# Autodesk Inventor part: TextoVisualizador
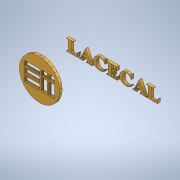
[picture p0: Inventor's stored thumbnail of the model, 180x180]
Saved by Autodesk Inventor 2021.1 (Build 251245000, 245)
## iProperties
Created: 2021-06
Part Number: TextoVisualizador
Material: Genérico
Document SubType Name: Modeling
Designer: Ricardo
Density: 1 g/cm^3
Appearance: Valor por defecto
Author: Ricardo
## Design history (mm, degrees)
sketch "Boceto1"
  geometry: L1 (-51.459, -7.217)-(-53.759, -7.217); L2 (-47.959, -7.217)-(-50.259, -7.217); L3 (-45.659, 2.183)-(-45.659, -2.517); L4 (-45.659, -7.217)-(-47.959, -7.217); L5 (-47.959, 2.183)-(-45.659, 2.183); L6 (-47.959, 7.383)-(-45.659, 7.383); L7 (-50.259, -2.517)-(-50.259, 2.183); L8 (-51.459, 7.383)-(-51.459, 5.358); L9 (-53.759, 7.383)-(-51.459, 7.383); L10 (-56.059, -2.517)-(-56.059, 2.183); L11 (-56.059, 7.383)-(-53.759, 7.383); L12 (-53.759, 3.333)-(-56.059, 3.333); L13 (-50.259, 5.358)-(-50.259, 7.383); L14 (-56.059, 5.358)-(-56.059, 7.383); L15 (32, -25.5)-(32, 25.5); L16 (-73.2, -43.7)-(73.2, -43.7); L17 (73.2, 43.7)-(-73.2, 43.7); L18 (73.2, 43.7)-(-73.2, 43.7); L19 (77.187, 25.393)-(-77.213, 25.607); L20 (-77.187, 43.807)-(77.213, 43.593); L21 (32, 25.5)-(-37, 25.5); L22 (32, 25.5)-(-37, 25.5); L23 (32, 25.5)-(-37, 25.5); L24 (-37, -25.5)-(32, -25.5); L25 (-37, -25.5)-(32, -25.5); L26 (-37, 25.5)-(-37, -25.5); L27 (-45.659, -2.517)-(-45.659, -7.217); L28 (-37, 25.5)-(-37, -25.5); L29 (-51.459, 3.333)-(-53.759, 3.333); L30 (-47.959, 3.333)-(-50.259, 3.333); L31 (-50.259, 3.333)-(-50.259, 5.358); L32 (-51.459, 5.358)-(-51.459, 3.333); L33 (77.213, 43.593)-(77.187, 25.393); L34 (32, -25.5)-(32, 25.5); L35 (77.2, -39.7)-(77.2, 39.7); L36 (-56.059, 3.333)-(-56.059, 5.358); L37 (-63.309, 7.383)-(-57.259, 7.383); L38 (-57.259, 5.358)-(-57.259, 3.333); L39 (-57.259, 3.333)-(-63.309, 3.333); L40 (-63.309, 3.333)-(-69.359, 3.333); L41 (-69.359, 3.333)-(-69.359, 5.358); L42 (-57.259, 7.383)-(-57.259, 5.358); L43 (-57.259, 2.183)-(-57.259, 0.158); L44 (-69.359, 5.358)-(-69.359, 7.383); L45 (-69.359, 7.383)-(-63.309, 7.383); L46 (-57.259, 0.158)-(-57.259, -1.867); L47 (-69.359, 0.158)-(-69.359, 2.183); L48 (-77.213, 25.607)-(-77.187, 43.807); L49 (-69.359, -5.142)-(-69.359, -3.067); L50 (-45.659, 5.358)-(-45.659, 3.333); L51 (-45.659, 7.383)-(-45.659, 5.358); L52 (-45.659, 3.333)-(-47.959, 3.333); L53 (-50.259, 2.183)-(-47.959, 2.183); L54 (-50.259, 7.383)-(-47.959, 7.383); L55 (-50.259, -7.217)-(-50.259, -2.517); L56 (-51.459, -2.517)-(-51.459, -7.217); L57 (-53.759, 2.183)-(-51.459, 2.183); L58 (-77.2, 39.7)-(-77.2, -39.7); L59 (-77.2, 39.7)-(-77.2, -39.7); L60 (-56.059, -7.217)-(-56.059, -2.517); L61 (-53.759, -7.217)-(-56.059, -7.217); L62 (-56.059, 2.183)-(-53.759, 2.183); L63 (-57.259, -5.142)-(-57.259, -7.217); L64 (-57.259, -7.217)-(-63.309, -7.217)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; A1 r 15.56 centre (-57.413, -0.174) between (-54.809, -15.515) and (-51.71, -14.652); A2 r 15.79 centre (-57.497, 0.039) between (-51.71, -14.652) and (-48.843, -13.168); A3 r 12.215 centre (-57.048, -3.501) between (-56.097, -15.68) and (-55.479, -15.616); A4 r 25.644 centre (-57.509, 9.918) between (-57.509, -15.726) and (-56.746, -15.715); A5 r 25.644 centre (-57.509, 9.918) between (-58.271, -15.715) and (-57.509, -15.726); A6 r 17.208 centre (-57.328, 1.45) between (-60.209, -15.515) and (-59.538, -15.616); A7 r 15.892 centre (-57.464, 0.128) between (-66.699, -12.805) and (-63.597, -14.533); A8 r 15.874 centre (-57.543, 0.11) between (-48.843, -13.168) and (-46.33, -11.127); A9 r 13.497 centre (-57.147, -2.224) between (-56.746, -15.715) and (-56.097, -15.68); A10 r 15.775 centre (-57.44, 0.094) between (-43.583, 7.634) and (-45.63, 10.553); A11 r 15.999 centre (-57.607, -0.054) between (-45.63, 10.553) and (-48.286, 12.949); A12 r 15.94 centre (-57.573, -0.006) between (-48.286, 12.949) and (-51.403, 14.691); A13 r 15.52 centre (-57.411, 0.381) between (-51.403, 14.691) and (-54.809, 15.682); A14 r 12.803 centre (-56.955, 3.06) between (-54.809, 15.682) and (-55.582, 15.789); A15 r 21.426 centre (-57.88, -5.513) between (-55.582, 15.789) and (-56.467, 15.866); A16 r 21.199 centre (-57.865, -5.287) between (-56.467, 15.866) and (-57.348, 15.906); A17 r 11.738 centre (-57.634, 4.172) between (-57.348, 15.906) and (-58.109, 15.9); A18 r 16.059 centre (-57.738, 0.085) between (-41.884, -2.475) and (-41.705, 1.006); A19 r 16.003 centre (-57.681, 0.088) between (-41.705, 1.006) and (-42.281, 4.437); A20 r 15.753 centre (-57.435, 0.036) between (-42.81, -5.817) and (-41.884, -2.475); A21 r 13.497 centre (-57.87, -2.224) between (-58.92, -15.68) and (-58.271, -15.715); A22 r 12.215 centre (-57.97, -3.501) between (-59.538, -15.616) and (-58.92, -15.68); A23 r 16.079 centre (-57.459, -0.166) between (-58.109, 15.9) and (-62.885, 14.97); A24 r 15.75 centre (-57.57, 0.144) between (-62.885, 14.97) and (-67.136, 12.656); A25 r 16.009 centre (-57.396, 0.223) between (-69.35, -10.425) and (-66.699, -12.805); A26 r 13.045 centre (-55.008, -1.175) between (-43.83, -7.901) and (-43.46, -7.243); A27 r 15.747 centre (-57.571, 0.146) between (-67.136, 12.656) and (-70.483, 9.16); A28 r 17.208 centre (-57.689, 1.45) between (-55.479, -15.616) and (-54.809, -15.515); A29 r 15.506 centre (-57.204, 0.223) between (-42.281, 4.437) and (-43.583, 7.634); A30 r 20.56 centre (-61.447, 2.699) between (-44.281, -8.617) and (-43.83, -7.901); A31 r 16.07 centre (-57.307, -0.039) between (-70.483, 9.16) and (-72.632, 4.796); A32 r 14.941 centre (-58.332, -0.292) between (-72.629, -4.632) and (-71.41, -7.517); A33 r 15.505 centre (-57.613, -0.229) between (-63.597, -14.533) and (-60.209, -15.515); A34 r 16.017 centre (-57.39, 0.229) between (-71.41, -7.517) and (-69.35, -10.425); A35 r 15.939 centre (-57.589, 0.156) between (-46.33, -11.127) and (-44.281, -8.617); A36 r 12.715 centre (-54.716, -1.329) between (-43.46, -7.243) and (-43.132, -6.572); A37 r 18.511 centre (-59.996, 1.061) between (-43.132, -6.572) and (-42.81, -5.817); A38 r 4 centre (73.2, 39.7) between (77.2, 39.7) and (73.2, 43.7); A39 r 4 centre (73.2, -39.7) between (73.2, -43.7) and (77.2, -39.7); A40 r 15.052 centre (-58.277, 0.267) between (-72.632, 4.796) and (-73.259, 1.72); A41 r 16.425 centre (-56.911, 0.135) between (-73.259, 1.72) and (-73.256, -1.488); A42 r 16.4 centre (-56.936, 0.132) between (-73.256, -1.488) and (-72.629, -4.632); A43 r 4 centre (-73.2, 39.7) between (-73.2, 43.7) and (-77.2, 39.7); A44 r 4 centre (-73.2, -39.7) between (-77.2, -39.7) and (-73.2, -43.7); 104 further points
  constraints: 142 end point, 88 point on circle, 44 centre point, 4 midpoint, 4 point on line, 2 other
extrude "Extrusión1" new body sketch "Boceto1" distance "d0" = 2; taper "d1" = 0 deg
node "Sólido1"
